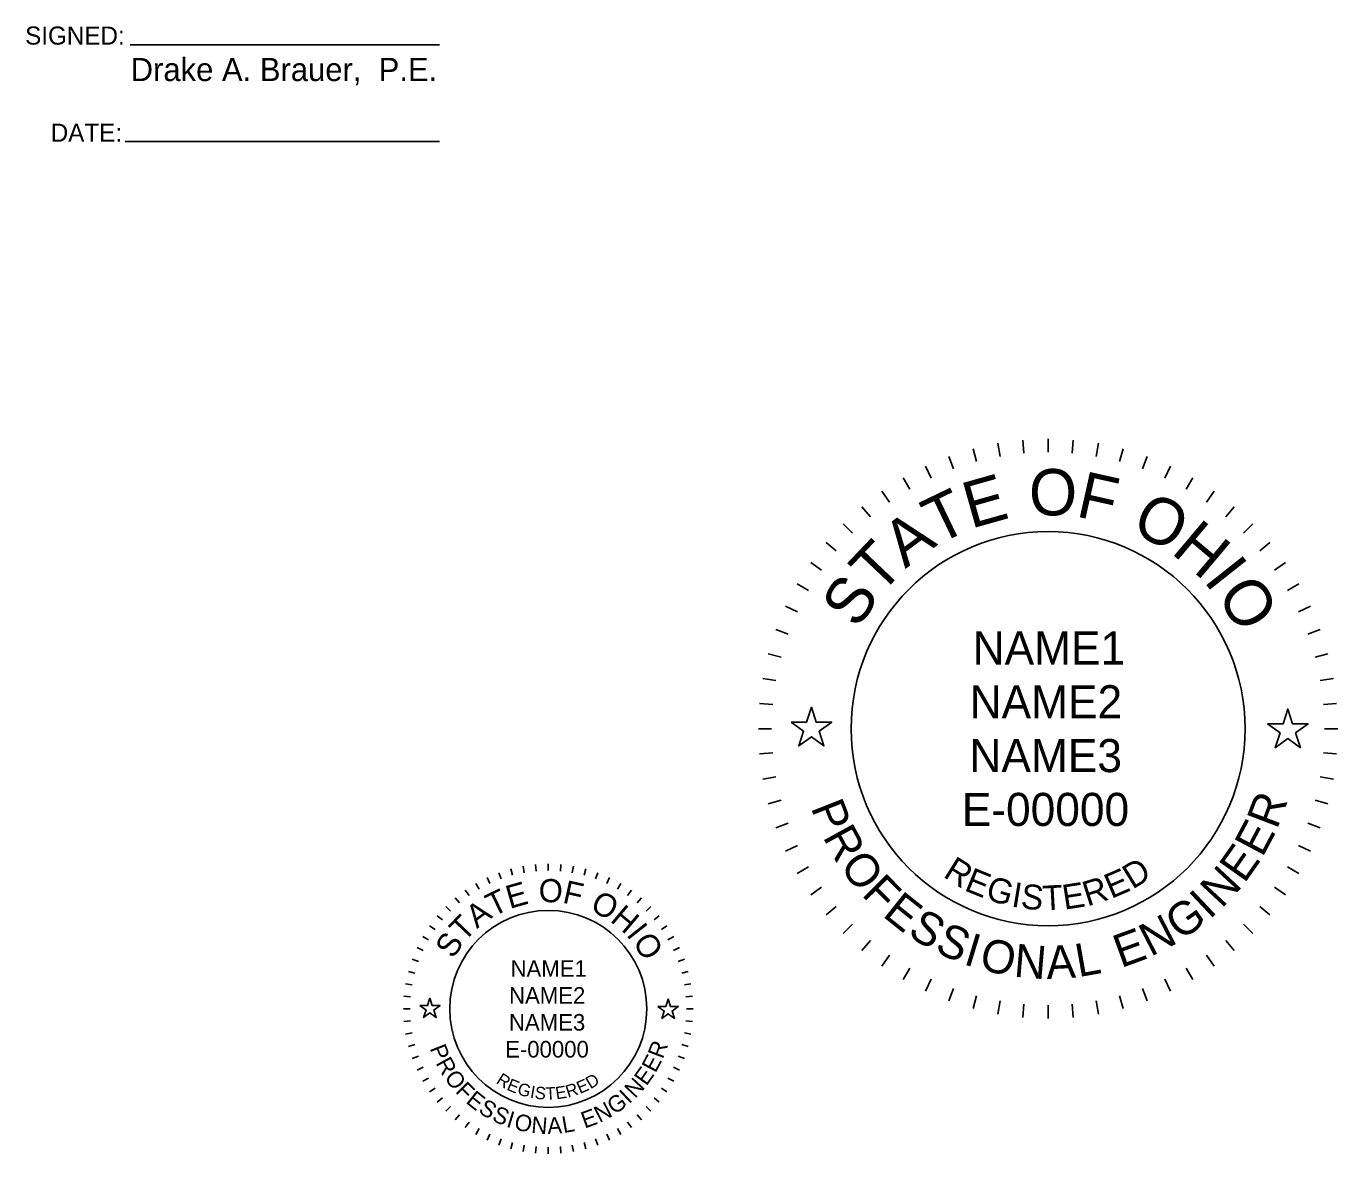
# Model space of a CAD drawing. Extents: x -17.5 to 72.9, y -57.8 to 32.3.
# Drawn here: x 25.46 to 33.39, y -7.49 to -0.68 of the extents above; entities that cross this region are included whole.
import ezdxf

# ---------------------------------------------------------------- set-up
doc = ezdxf.new("R2010")
doc.units = 0
doc.layers.add('SH_Data', color=7, linetype='Continuous')
doc.layers.add('SH_Text', color=7, linetype='Continuous')

msp = doc.modelspace()

# ---------------------------------------------------------------- linework, layer by layer
at = {"layer": 'SH_Data'}
for p, q in [((26.0906, -0.7948), (27.9602, -0.7948)), ((26.0606, -1.3778), (27.9602, -1.3778)), ((31.1833, -3.2345), (31.204, -3.3118)), ((31.3324, -3.2015), (31.3463, -3.2803)), ((31.4837, -3.1816), (31.4907, -3.2613)), ((31.6363, -3.1749), (31.6363, -3.2549)), ((31.7888, -3.1816), (31.7818, -3.2613)), ((31.9402, -3.2015), (31.9263, -3.2803)), ((32.0892, -3.2345), (32.0685, -3.3118)), ((31.0377, -3.2804), (31.0651, -3.3556)), ((32.2348, -3.2804), (32.2074, -3.3556)), ((30.8967, -3.3389), (30.9305, -3.4114)), ((32.3759, -3.3389), (32.342, -3.4114)), ((30.7613, -3.4094), (30.8013, -3.4786)), ((32.5113, -3.4094), (32.4713, -3.4786)), ((30.6325, -3.4914), (30.6784, -3.5569)), ((32.64, -3.4914), (32.5941, -3.5569)), ((30.5114, -3.5843), (30.5628, -3.6456)), ((32.7612, -3.5843), (32.7097, -3.6456)), ((30.3988, -3.6875), (30.4554, -3.744)), ((32.8737, -3.6875), (32.8171, -3.744)), ((30.2957, -3.8), (30.357, -3.8514)), ((32.9768, -3.8), (32.9156, -3.8514)), ((30.2028, -3.9211), (30.2683, -3.967)), ((33.0698, -3.9211), (33.0043, -3.967)), ((30.1207, -4.0499), (30.19, -4.0899)), ((33.1518, -4.0499), (33.0825, -4.0899)), ((30.0502, -4.1853), (30.1227, -4.2191)), ((33.2223, -4.1853), (33.1498, -4.2191)), ((29.9918, -4.3264), (30.067, -4.3537)), ((33.2807, -4.3264), (33.2056, -4.3537)), ((29.9459, -4.472), (30.0232, -4.4927)), ((33.3266, -4.472), (33.2494, -4.4927)), ((29.9129, -4.621), (29.9916, -4.6349)), ((33.3597, -4.621), (33.2809, -4.6349)), ((29.8929, -4.7724), (29.9726, -4.7793)), ((33.3796, -4.7724), (33.2999, -4.7793)), ((29.8863, -4.9249), (29.9663, -4.9249)), ((33.3863, -4.9249), (33.3063, -4.9249)), ((29.8929, -5.0774), (29.9726, -5.0704)), ((33.3796, -5.0774), (33.2999, -5.0704)), ((29.9129, -5.2288), (29.9916, -5.2149)), ((33.3597, -5.2288), (33.2809, -5.2149)), ((29.9459, -5.3778), (30.0232, -5.3571)), ((33.3266, -5.3778), (33.2494, -5.3571)), ((29.9918, -5.5234), (30.067, -5.4961)), ((33.2807, -5.5234), (33.2056, -5.4961)), ((30.0502, -5.6645), (30.1227, -5.6307)), ((33.2223, -5.6645), (33.1498, -5.6307)), ((28.3906, -5.7719), (28.401, -5.8105)), ((28.4652, -5.7554), (28.4721, -5.7948)), ((28.5408, -5.7454), (28.5443, -5.7852)), ((28.6171, -5.7421), (28.6171, -5.7821)), ((28.6934, -5.7454), (28.6899, -5.7852)), ((28.769, -5.7554), (28.7621, -5.7948)), ((28.8436, -5.7719), (28.8332, -5.8105)), ((30.1207, -5.7999), (30.19, -5.7599)), ((33.1518, -5.7999), (33.0825, -5.7599)), ((28.1796, -5.8593), (28.1996, -5.8939)), ((28.2473, -5.8241), (28.2642, -5.8603)), ((28.3178, -5.7948), (28.3315, -5.8324)), ((28.9164, -5.7948), (28.9027, -5.8324)), ((28.9869, -5.8241), (28.97, -5.8603)), ((29.0546, -5.8593), (29.0346, -5.8939)), ((28.1152, -5.9003), (28.1382, -5.9331)), ((29.119, -5.9003), (29.096, -5.9331)), ((30.2028, -5.9287), (30.2683, -5.8828)), ((33.0698, -5.9287), (33.0043, -5.8828)), ((27.9984, -5.9984), (28.0267, -6.0266)), ((28.0547, -5.9468), (28.0804, -5.9774)), ((29.1795, -5.9468), (29.1538, -5.9774)), ((29.2358, -5.9984), (29.2075, -6.0266)), ((30.2957, -6.0498), (30.357, -5.9984)), ((32.9768, -6.0498), (32.9156, -5.9984)), ((27.9468, -6.0546), (27.9774, -6.0803)), ((29.2874, -6.0546), (29.2567, -6.0803)), ((27.8593, -6.1796), (27.894, -6.1996)), ((27.9003, -6.1152), (27.9331, -6.1381)), ((29.3339, -6.1152), (29.3011, -6.1381)), ((29.3749, -6.1796), (29.3402, -6.1996)), ((30.3988, -6.1623), (30.4554, -6.1058)), ((32.8737, -6.1623), (32.8171, -6.1058)), ((27.8241, -6.2473), (27.8603, -6.2642)), ((29.4101, -6.2473), (29.3739, -6.2642)), ((30.5114, -6.2655), (30.5628, -6.2042)), ((32.7612, -6.2655), (32.7097, -6.2042)), ((27.7949, -6.3178), (27.8325, -6.3315)), ((29.4393, -6.3178), (29.4017, -6.3315)), ((30.6325, -6.3584), (30.6784, -6.2929)), ((32.64, -6.3584), (32.5941, -6.2929)), ((27.7719, -6.3906), (27.8105, -6.401)), ((29.4623, -6.3906), (29.4236, -6.401)), ((30.7613, -6.4404), (30.8013, -6.3712)), ((32.5113, -6.4404), (32.4713, -6.3712)), ((27.7554, -6.4651), (27.7948, -6.4721)), ((29.4788, -6.4651), (29.4394, -6.4721)), ((30.8967, -6.5109), (30.9305, -6.4384)), ((31.0377, -6.5694), (31.0651, -6.4942)), ((32.2348, -6.5694), (32.2074, -6.4942)), ((32.3759, -6.5109), (32.342, -6.4384)), ((27.7454, -6.5408), (27.7853, -6.5443)), ((29.4888, -6.5408), (29.4489, -6.5443)), ((31.1833, -6.6153), (31.204, -6.538)), ((31.3324, -6.6483), (31.3463, -6.5695)), ((31.9402, -6.6483), (31.9263, -6.5695)), ((32.0892, -6.6153), (32.0685, -6.538)), ((27.7421, -6.6171), (27.7821, -6.6171)), ((29.4921, -6.6171), (29.4521, -6.6171)), ((31.4837, -6.6682), (31.4907, -6.5885)), ((31.6363, -6.6749), (31.6363, -6.5949)), ((31.7888, -6.6682), (31.7818, -6.5885)), ((27.7454, -6.6933), (27.7853, -6.6898)), ((29.4888, -6.6933), (29.4489, -6.6898)), ((27.7554, -6.769), (27.7948, -6.7621)), ((29.4788, -6.769), (29.4394, -6.7621)), ((27.7719, -6.8435), (27.8105, -6.8332)), ((29.4623, -6.8435), (29.4236, -6.8332)), ((27.7949, -6.9163), (27.8325, -6.9027)), ((27.8241, -6.9869), (27.8603, -6.97)), ((29.4101, -6.9869), (29.3739, -6.97)), ((29.4393, -6.9163), (29.4017, -6.9027)), ((27.8593, -7.0546), (27.894, -7.0346)), ((29.3749, -7.0546), (29.3402, -7.0346)), ((27.9003, -7.119), (27.9331, -7.096)), ((29.3339, -7.119), (29.3011, -7.096)), ((27.9468, -7.1795), (27.9774, -7.1538)), ((27.9984, -7.2358), (28.0267, -7.2075)), ((29.2358, -7.2358), (29.2075, -7.2075)), ((29.2874, -7.1795), (29.2567, -7.1538)), ((28.0547, -7.2874), (28.0804, -7.2567)), ((29.1795, -7.2874), (29.1538, -7.2567)), ((28.1152, -7.3338), (28.1382, -7.3011)), ((28.1796, -7.3748), (28.1996, -7.3402)), ((29.0546, -7.3748), (29.0346, -7.3402)), ((29.119, -7.3338), (29.096, -7.3011)), ((28.2473, -7.4101), (28.2642, -7.3738)), ((28.3178, -7.4393), (28.3315, -7.4017)), ((28.3906, -7.4623), (28.401, -7.4236)), ((28.4652, -7.4788), (28.4721, -7.4394)), ((28.769, -7.4788), (28.7621, -7.4394)), ((28.8436, -7.4623), (28.8332, -7.4236)), ((28.9164, -7.4393), (28.9027, -7.4017)), ((28.9869, -7.4101), (28.97, -7.3738)), ((28.5408, -7.4887), (28.5443, -7.4489)), ((28.6171, -7.4921), (28.6171, -7.4521)), ((28.6934, -7.4887), (28.6899, -7.4489))]:
    msp.add_line(p, q, dxfattribs=at)
for points in [[(30.0835, -4.885), (30.1773, -4.885), (30.2063, -4.7958), (30.2353, -4.885), (30.329, -4.885), (30.2532, -4.9402), (30.2822, -5.0293), (30.2063, -4.9742), (30.1303, -5.0293), (30.1593, -4.9402)], [(32.9617, -4.8957), (33.0555, -4.8957), (33.0845, -4.8066), (33.1135, -4.8957), (33.2072, -4.8957), (33.1315, -4.9509), (33.1604, -5.0401), (33.0845, -4.9849), (33.0085, -5.0401), (33.0375, -4.9509)], [(27.8407, -6.5971), (27.8876, -6.5971), (27.9021, -6.5525), (27.9166, -6.5971), (27.9635, -6.5971), (27.9256, -6.6247), (27.9401, -6.6693), (27.9021, -6.6417), (27.8641, -6.6693), (27.8786, -6.6247)], [(29.2798, -6.6025), (29.3267, -6.6025), (29.3412, -6.5579), (29.3557, -6.6025), (29.4026, -6.6025), (29.3647, -6.6301), (29.3792, -6.6747), (29.3412, -6.6471), (29.3032, -6.6747), (29.3177, -6.6301)]]:
    msp.add_lwpolyline(points, close=True, dxfattribs=at)
for centre, radius in [((31.6363, -4.9249), 1.19), ((28.6171, -6.6171), 0.595)]:
    msp.add_circle(centre, radius, dxfattribs=at)

# ---------------------------------------------------------------- texts
for s, height, p in [('SIGNED:', 0.10938, (25.4568, -0.7937)), ('DATE:', 0.10938, (25.6115, -1.3803)), ('NAME1', 0.2, (31.1806, -4.5374)), ('NAME2', 0.2, (31.1623, -4.8624)), ('NAME3', 0.2, (31.1612, -5.1874)), ('E-00000', 0.2, (31.1149, -5.5124)), ('NAME1', 0.1, (28.3892, -6.4233)), ('NAME2', 0.1, (28.3801, -6.5858)), ('NAME3', 0.1, (28.3796, -6.7483)), ('E-00000', 0.1, (28.3564, -6.9108))]:
    msp.add_text(s, height=height, dxfattribs=at).set_placement(p)
for s, height, rotation, p in [('E', 0.28, 15.75706, (31.1701, -3.7181)), ('O', 0.28, 359.78119, (31.5203, -3.6364)), ('F', 0.28, 347.43619, (31.7984, -3.6414)), ('T', 0.28, 25.71674, (30.9684, -3.8169)), ('O', 0.28, 332.25863, (32.1288, -3.7287)), ('A', 0.28, 36.47472, (30.7734, -3.9611)), ('H', 0.28, 319.91363, (32.3732, -3.8616)), ('T', 0.28, 46.4344, (30.6197, -4.1248)), ('I', 0.28, 308.36695, (32.5711, -4.0306)), ('S', 0.28, 57.19238, (30.4882, -4.3287)), ('O', 0.28, 303.14906, (32.6485, -4.1194)), ('P', 0.2, 291.49398, (30.201, -5.4012)), ('R', 0.2, 69.23216, (33.0188, -5.5377)), ('R', 0.2, 298.73106, (30.2724, -5.5782)), ('E', 0.2, 61.99508, (32.9306, -5.707)), ('E', 0.2, 54.75801, (32.8218, -5.8638)), ('O', 0.2, 306.46664, (30.3728, -5.7558)), ('R', 0.15, 327.82385, (30.9965, -5.8169)), ('E', 0.15, 337.77772, (31.1242, -5.8994)), ('E', 0.15, 23.30524, (32.0181, -5.9537)), ('D', 0.15, 31.46601, (32.1464, -5.8976)), ('N', 0.2, 47.02243, (32.6846, -6.0148)), ('E', 0.14, 15.75706, (28.384, -6.0137)), ('O', 0.14, 359.78119, (28.5591, -5.9728)), ('F', 0.14, 347.43619, (28.6982, -5.9753)), ('F', 0.2, 314.7068, (30.5049, -5.9284)), ('G', 0.15, 344.27273, (31.2527, -5.9553)), ('I', 0.15, 350.64643, (31.41, -5.9982)), ('S', 0.15, 353.78581, (31.4672, -6.0088)), ('E', 0.15, 8.98261, (31.7347, -6.0188)), ('R', 0.15, 17.68363, (31.8737, -5.9994)), ('T', 0.14, 25.71674, (28.2832, -6.0631)), ('O', 0.14, 332.25863, (28.8634, -6.019)), ('E', 0.2, 321.43929, (30.6303, -6.0541)), ('T', 0.15, 3.00609, (31.6066, -6.0238)), ('I', 0.2, 43.28703, (32.6114, -6.0808)), ('A', 0.14, 36.47472, (28.1856, -6.1352)), ('H', 0.14, 319.91363, (28.9855, -6.0854)), ('G', 0.2, 35.04687, (32.4357, -6.2086)), ('T', 0.14, 46.4344, (28.1088, -6.217)), ('I', 0.14, 308.36695, (29.0845, -6.1699)), ('S', 0.2, 328.67637, (30.7806, -6.1718)), ('N', 0.2, 27.31129, (32.2556, -6.3045)), ('S', 0.14, 57.19238, (28.0431, -6.319)), ('O', 0.14, 303.14906, (29.1232, -6.2143)), ('S', 0.2, 335.91345, (30.9445, -6.2697)), ('I', 0.2, 343.15053, (31.1194, -6.3461)), ('E', 0.2, 20.07421, (32.0769, -6.3716)), ('O', 0.2, 346.88592, (31.2131, -6.3767)), ('N', 0.2, 355.12608, (31.4255, -6.4224)), ('A', 0.2, 2.86166, (31.629, -6.4371)), ('L', 0.2, 10.09874, (31.8196, -6.426)), ('R', 0.1, 69.23216, (29.3084, -6.9235)), ('P', 0.1, 291.49398, (27.8994, -6.8552)), ('E', 0.1, 61.99508, (29.2643, -7.0081)), ('R', 0.1, 298.73106, (27.9352, -6.9437)), ('E', 0.1, 54.75801, (29.2099, -7.0865)), ('O', 0.1, 306.46664, (27.9853, -7.0325)), ('R', 0.075, 327.82385, (28.2972, -7.0631)), ('E', 0.075, 337.77772, (28.361, -7.1043)), ('E', 0.075, 23.30524, (28.808, -7.1315)), ('D', 0.075, 31.46601, (28.8721, -7.1034)), ('N', 0.1, 47.02243, (29.1413, -7.162)), ('F', 0.1, 314.7068, (28.0514, -7.1188)), ('E', 0.1, 321.43929, (28.1141, -7.1817)), ('G', 0.075, 344.27273, (28.4253, -7.1323)), ('I', 0.075, 350.64643, (28.5039, -7.1537)), ('S', 0.075, 353.78581, (28.5326, -7.159)), ('T', 0.075, 3.00609, (28.6022, -7.1665)), ('E', 0.075, 8.98261, (28.6663, -7.164)), ('R', 0.075, 17.68363, (28.7358, -7.1543)), ('I', 0.1, 43.28703, (29.1047, -7.195)), ('S', 0.1, 328.67637, (28.1893, -7.2405)), ('S', 0.1, 335.91345, (28.2712, -7.2895)), ('N', 0.1, 27.31129, (28.9268, -7.3069)), ('G', 0.1, 35.04687, (29.0168, -7.2589)), ('I', 0.1, 343.15053, (28.3587, -7.3277)), ('O', 0.1, 346.88592, (28.4055, -7.343)), ('N', 0.1, 355.12608, (28.5117, -7.3658)), ('A', 0.1, 2.86166, (28.6135, -7.3732)), ('L', 0.1, 10.09874, (28.7088, -7.3676)), ('E', 0.1, 20.07421, (28.8374, -7.3404))]:
    msp.add_text(s, height=height, rotation=rotation, dxfattribs=at).set_placement(p)
at = {"layer": 'SH_Text'}
msp.add_text('Drake A. Brauer,  P.E.', height=0.14, dxfattribs=at).set_placement((26.0943, -1.0139))

doc.saveas('drawing.dxf')
